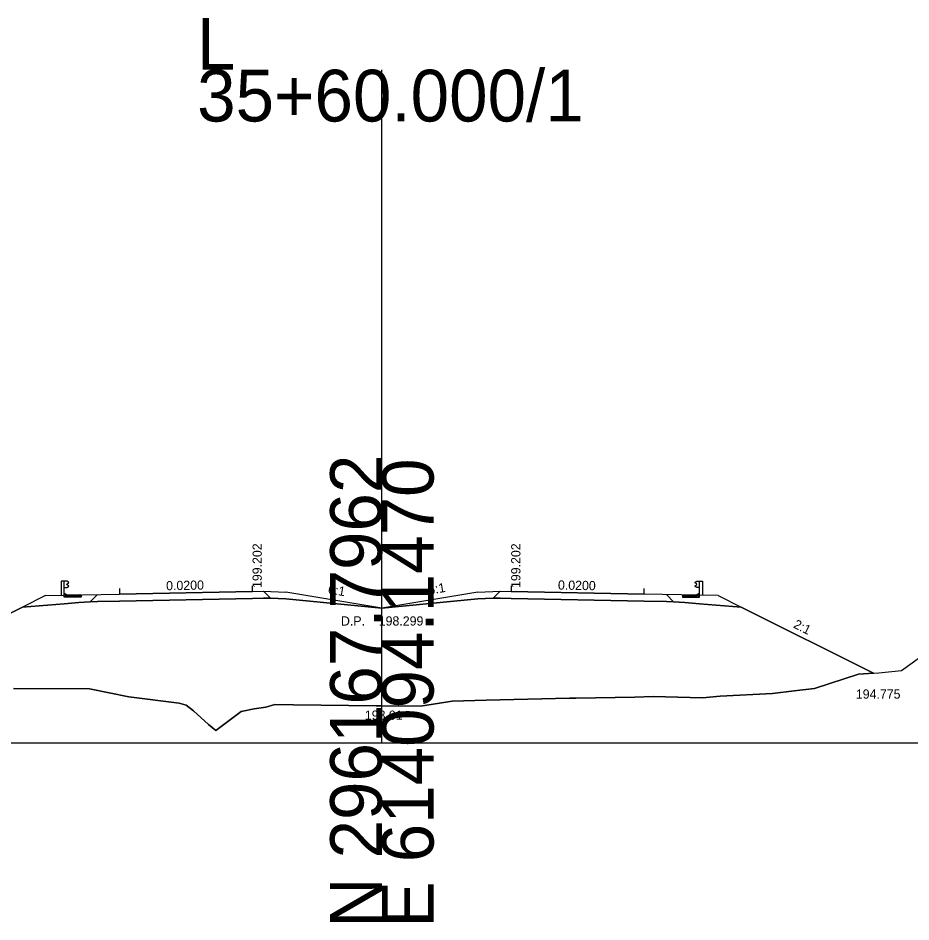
# Model space of a CAD drawing. Extents: x -81 to 616364, y 450 to 299952.
# Drawn here: x 541507.67 to 541556, y 118838.67 to 118887.61 of the extents above; entities that cross this region are included whole.
import ezdxf

# ---------------------------------------------------------------- set-up
doc = ezdxf.new("R2010")
doc.units = 0
for name, color, linetype in [('Exist XS Ground Line', 7, 'Continuous'), ('Old_Level_2', 7, 'Continuous'), ('Old_Level_3', 7, 'Continuous'), ('Old_Level_6', 7, 'Continuous'), ('Old_Level_63', 7, 'Continuous'), ('Prop XS Dump Level', 7, 'Continuous'), ('Prop XS Earthwork Shape', 7, 'Continuous'), ('Prop XS EOT Tick Mark', 7, 'Continuous'), ('Prop XS Finish Grade', 7, 'Continuous'), ('Prop XS Finish Grade Earthwork', 7, 'Continuous'), ('Prop XS Finish Grade Pavement', 7, 'Continuous'), ('Prop XS Label Text', 7, 'Continuous'), ('Prop XS Pvmt Edge Slope', 7, 'Continuous'), ('Prop XS Side Slope Text', 7, 'Continuous'), ('Prop XS Subgrade Earthwork', 7, 'Continuous')]:
    doc.layers.add(name, color=color, linetype=linetype)

msp = doc.modelspace()

# ---------------------------------------------------------------- linework, layer by layer
at = {"layer": 'Exist XS Ground Line'}
for p, q in [((541555.484, 118852.277), (541556.52, 118853.02)), ((541550.777, 118851.318), (541553.156, 118852.079)), ((541553.156, 118852.079), (541554.273, 118852.162)), ((541554.273, 118852.162), (541555.484, 118852.277)), ((541507.431, 118851.309), (541511.535, 118851.293)), ((541511.535, 118851.293), (541513.67, 118850.865)), ((541545.68, 118850.894), (541548.515, 118851.032)), ((541548.515, 118851.032), (541549.676, 118851.185)), ((541549.676, 118851.185), (541550.777, 118851.318)), ((541513.67, 118850.865), (541516.385, 118850.51)), ((541516.385, 118850.51), (541516.774, 118850.415)), ((541529.462, 118850.355), (541531.169, 118850.632)), ((541531.169, 118850.632), (541533.005, 118850.687)), ((541533.005, 118850.687), (541537.522, 118850.789)), ((541537.522, 118850.789), (541537.856, 118850.787)), ((541537.856, 118850.787), (541541.056, 118850.843)), ((541541.056, 118850.843), (541542.048, 118850.873)), ((541542.048, 118850.873), (541544.724, 118850.801)), ((541544.724, 118850.801), (541545.68, 118850.894)), ((541516.774, 118850.415), (541517.174, 118850.099)), ((541517.174, 118850.099), (541517.989, 118849.354)), ((541518.375, 118849.042), (541519.743, 118850.062)), ((541519.743, 118850.062), (541520.457, 118850.213)), ((541520.457, 118850.213), (541521.086, 118850.308)), ((541521.086, 118850.308), (541521.562, 118850.441)), ((541521.562, 118850.441), (541522.586, 118850.431)), ((541522.586, 118850.431), (541527.062, 118850.381)), ((541527.062, 118850.381), (541527.365, 118850.378)), ((541527.365, 118850.378), (541529.462, 118850.355)), ((541517.989, 118849.354), (541518.375, 118849.042))]:
    msp.add_line(p, q, dxfattribs=at)
at = {"layer": 'Old_Level_2'}
for p, q in [((541543.645, 118856.385), (541543.645, 118856.26)), ((541543.645, 118856.385), (541544.355, 118856.36)), ((541543.692, 118856.363), (541543.667, 118856.345)), ((541543.667, 118856.345), (541543.707, 118856.335)), ((541543.707, 118856.335), (541543.692, 118856.363)), ((541543.882, 118856.326), (541543.873, 118856.298)), ((541543.903, 118856.296), (541543.882, 118856.326)), ((541544.01, 118856.344), (541543.985, 118856.326)), ((541543.985, 118856.326), (541544.025, 118856.316)), ((541544.025, 118856.316), (541544.01, 118856.344)), ((541544.186, 118856.326), (541544.178, 118856.298)), ((541544.207, 118856.296), (541544.186, 118856.326)), ((541544.565, 118856.465), (541544.355, 118856.36)), ((541544.468, 118856.35), (541544.506, 118856.361)), ((541544.502, 118856.338), (541544.468, 118856.35)), ((541544.506, 118856.361), (541544.502, 118856.338)), ((541544.565, 118856.26), (541544.565, 118856.465)), ((541543.645, 118856.26), (541544.565, 118856.26)), ((541543.8, 118856.312), (541543.775, 118856.294)), ((541543.775, 118856.294), (541543.816, 118856.285)), ((541543.816, 118856.285), (541543.8, 118856.312)), ((541543.873, 118856.298), (541543.903, 118856.296)), ((541544.105, 118856.312), (541544.08, 118856.294)), ((541544.08, 118856.294), (541544.12, 118856.285)), ((541544.12, 118856.285), (541544.105, 118856.312)), ((541544.178, 118856.298), (541544.207, 118856.296)), ((541544.31, 118856.312), (541544.285, 118856.294)), ((541544.285, 118856.294), (541544.325, 118856.284)), ((541544.325, 118856.284), (541544.31, 118856.312)), ((541544.409, 118856.312), (541544.384, 118856.294)), ((541544.384, 118856.294), (541544.425, 118856.285)), ((541544.425, 118856.285), (541544.409, 118856.312))]:
    msp.add_line(p, q, dxfattribs=at)
for centre in [(541543.653, 118856.344), (541543.658, 118856.32), (541543.661, 118856.375), (541543.706, 118856.376), (541543.708, 118856.32), (541543.73, 118856.356), (541543.74, 118856.336), (541543.749, 118856.373), (541543.753, 118856.344), (541543.757, 118856.321), (541543.773, 118856.316), (541543.779, 118856.371), (541543.797, 118856.351), (541543.8, 118856.344), (541543.822, 118856.315), (541543.84, 118856.33), (541543.847, 118856.355), (541543.871, 118856.367), (541543.873, 118856.317), (541543.894, 118856.345), (541543.896, 118856.351), (541543.928, 118856.366), (541543.94, 118856.331), (541543.944, 118856.335), (541543.958, 118856.344), (541543.962, 118856.32), (541543.989, 118856.366), (541544.029, 118856.354), (541544.044, 118856.336), (541544.058, 118856.344), (541544.062, 118856.321), (541544.063, 118856.362), (541544.078, 118856.316), (541544.105, 118856.344), (541544.138, 118856.351), (541544.144, 118856.33), (541544.177, 118856.317), (541544.178, 118856.354), (541544.199, 118856.345), (541544.226, 118856.327), (541544.244, 118856.331), (541544.249, 118856.335), (541544.262, 118856.344), (541544.267, 118856.32), (541544.295, 118856.324), (541544.298, 118856.346), (541544.31, 118856.344), (541544.339, 118856.356), (541544.349, 118856.336), (541544.362, 118856.344), (541544.366, 118856.321), (541544.382, 118856.316), (541544.397, 118856.365), (541544.404, 118856.335), (541544.429, 118856.34), (541544.435, 118856.373), (541544.454, 118856.337), (541544.464, 118856.395), (541544.475, 118856.371), (541544.486, 118856.383), (541544.49, 118856.359), (541544.491, 118856.322), (541544.496, 118856.411), (541544.523, 118856.356), (541544.525, 118856.382), (541544.528, 118856.316), (541544.546, 118856.392), (541544.548, 118856.44), (541544.55, 118856.344), (541543.661, 118856.274), (541543.68, 118856.306), (541543.702, 118856.279), (541543.72, 118856.297), (541543.743, 118856.286), (541543.77, 118856.274), (541543.795, 118856.271), (541543.823, 118856.276), (541543.846, 118856.3), (541543.867, 118856.271), (541543.895, 118856.272), (541543.903, 118856.31), (541543.925, 118856.296), (541543.942, 118856.271), (541543.948, 118856.285), (541543.973, 118856.295), (541543.984, 118856.272), (541543.998, 118856.306), (541544.019, 118856.27), (541544.024, 118856.297), (541544.048, 118856.286), (541544.1, 118856.271), (541544.136, 118856.301), (541544.156, 118856.279), (541544.2, 118856.272), (541544.208, 118856.31), (541544.229, 118856.296), (541544.231, 118856.272), (541544.253, 118856.285), (541544.287, 118856.272), (541544.329, 118856.297), (541544.352, 118856.286), (541544.404, 118856.271), (541544.444, 118856.304), (541544.445, 118856.269), (541544.47, 118856.278), (541544.495, 118856.31), (541544.499, 118856.304), (541544.512, 118856.275), (541544.548, 118856.279)]:
    msp.add_circle(centre, 0.00196, dxfattribs=at)
for centre, start, end in [((541543.83, 118856.357), 170.2002, 7.8003), ((541543.947, 118856.355), 188.5188, 349.4817), ((541544.101, 118856.351), 124.5837, 53.4168), ((541544.201, 118856.351), 206.3348, 331.6657), ((541544.251, 118856.355), 269.9741, 330.0388), ((541544.536, 118856.406), 131.0057, 228.9943), ((541543.644, 118856.285), 307.9938, 52.0062), ((541543.738, 118856.259), 49.2889, 130.7111), ((541543.838, 118856.26), 21.9976, 158.0024), ((541544.043, 118856.259), 49.2889, 130.7111), ((541544.142, 118856.26), 21.9976, 158.0024), ((541544.347, 118856.259), 49.2889, 130.7111)]:
    msp.add_arc(centre, 0.00196, start, end, dxfattribs=at)
at = {"layer": 'Old_Level_3'}
for p, q in [((541510.165, 118856.465), (541510.375, 118856.36)), ((541510.165, 118856.26), (541510.165, 118856.465)), ((541510.224, 118856.361), (541510.228, 118856.338)), ((541510.261, 118856.35), (541510.224, 118856.361)), ((541510.228, 118856.338), (541510.261, 118856.35)), ((541511.085, 118856.385), (541510.375, 118856.36)), ((541510.523, 118856.296), (541510.544, 118856.326)), ((541510.544, 118856.326), (541510.552, 118856.298)), ((541510.705, 118856.316), (541510.72, 118856.344)), ((541510.745, 118856.326), (541510.705, 118856.316)), ((541510.72, 118856.344), (541510.745, 118856.326)), ((541510.827, 118856.296), (541510.848, 118856.326)), ((541510.848, 118856.326), (541510.856, 118856.298)), ((541511.022, 118856.335), (541511.038, 118856.363)), ((541511.063, 118856.345), (541511.022, 118856.335)), ((541511.038, 118856.363), (541511.063, 118856.345)), ((541511.085, 118856.385), (541511.085, 118856.26)), ((541511.085, 118856.26), (541510.165, 118856.26)), ((541510.305, 118856.285), (541510.32, 118856.312)), ((541510.345, 118856.294), (541510.305, 118856.285)), ((541510.32, 118856.312), (541510.345, 118856.294)), ((541510.405, 118856.284), (541510.42, 118856.312)), ((541510.445, 118856.294), (541510.405, 118856.284)), ((541510.42, 118856.312), (541510.445, 118856.294)), ((541510.552, 118856.298), (541510.523, 118856.296)), ((541510.609, 118856.285), (541510.625, 118856.312)), ((541510.65, 118856.294), (541510.609, 118856.285)), ((541510.625, 118856.312), (541510.65, 118856.294)), ((541510.856, 118856.298), (541510.827, 118856.296)), ((541510.914, 118856.285), (541510.929, 118856.312)), ((541510.954, 118856.294), (541510.914, 118856.285)), ((541510.929, 118856.312), (541510.954, 118856.294))]:
    msp.add_line(p, q, dxfattribs=at)
for centre in [(541510.179, 118856.344), (541510.182, 118856.44), (541510.184, 118856.392), (541510.201, 118856.316), (541510.205, 118856.382), (541510.206, 118856.356), (541510.234, 118856.411), (541510.238, 118856.322), (541510.24, 118856.359), (541510.244, 118856.383), (541510.254, 118856.371), (541510.266, 118856.395), (541510.276, 118856.337), (541510.294, 118856.373), (541510.301, 118856.34), (541510.326, 118856.335), (541510.333, 118856.365), (541510.348, 118856.316), (541510.363, 118856.321), (541510.368, 118856.344), (541510.381, 118856.336), (541510.391, 118856.356), (541510.42, 118856.344), (541510.431, 118856.346), (541510.434, 118856.324), (541510.463, 118856.32), (541510.467, 118856.344), (541510.481, 118856.335), (541510.486, 118856.331), (541510.503, 118856.327), (541510.531, 118856.345), (541510.551, 118856.354), (541510.552, 118856.317), (541510.585, 118856.33), (541510.592, 118856.351), (541510.625, 118856.344), (541510.652, 118856.316), (541510.666, 118856.362), (541510.668, 118856.321), (541510.672, 118856.344), (541510.686, 118856.336), (541510.7, 118856.354), (541510.741, 118856.366), (541510.768, 118856.32), (541510.772, 118856.344), (541510.785, 118856.335), (541510.79, 118856.331), (541510.802, 118856.366), (541510.833, 118856.351), (541510.835, 118856.345), (541510.857, 118856.317), (541510.859, 118856.367), (541510.883, 118856.355), (541510.89, 118856.33), (541510.908, 118856.315), (541510.929, 118856.344), (541510.933, 118856.351), (541510.951, 118856.371), (541510.957, 118856.316), (541510.972, 118856.321), (541510.977, 118856.344), (541510.98, 118856.373), (541510.99, 118856.336), (541511, 118856.356), (541511.022, 118856.32), (541511.024, 118856.376), (541511.069, 118856.375), (541511.072, 118856.32), (541511.076, 118856.344), (541510.182, 118856.279), (541510.218, 118856.275), (541510.231, 118856.304), (541510.234, 118856.31), (541510.259, 118856.278), (541510.284, 118856.269), (541510.285, 118856.304), (541510.325, 118856.271), (541510.377, 118856.286), (541510.401, 118856.297), (541510.443, 118856.272), (541510.477, 118856.285), (541510.499, 118856.272), (541510.5, 118856.296), (541510.522, 118856.31), (541510.53, 118856.272), (541510.573, 118856.279), (541510.594, 118856.301), (541510.63, 118856.271), (541510.682, 118856.286), (541510.705, 118856.297), (541510.711, 118856.27), (541510.732, 118856.306), (541510.746, 118856.272), (541510.757, 118856.295), (541510.781, 118856.285), (541510.788, 118856.271), (541510.805, 118856.296), (541510.826, 118856.31), (541510.835, 118856.272), (541510.863, 118856.271), (541510.884, 118856.3), (541510.907, 118856.276), (541510.934, 118856.271), (541510.959, 118856.274), (541510.986, 118856.286), (541511.01, 118856.297), (541511.028, 118856.279), (541511.05, 118856.306), (541511.069, 118856.274)]:
    msp.add_circle(centre, 0.00196, dxfattribs=at)
for centre, start, end in [((541510.194, 118856.406), 311.0057, 48.9943), ((541510.479, 118856.355), 209.9612, 270.0259), ((541510.529, 118856.351), 208.3343, 333.6652), ((541510.628, 118856.351), 126.5832, 55.4163), ((541510.783, 118856.355), 190.5183, 351.4812), ((541510.9, 118856.357), 172.1997, 9.7998), ((541510.382, 118856.259), 49.2889, 130.7111), ((541510.587, 118856.26), 21.9976, 158.0024), ((541510.687, 118856.259), 49.2889, 130.7111), ((541510.892, 118856.26), 21.9976, 158.0024), ((541510.991, 118856.259), 49.2889, 130.7111), ((541511.086, 118856.285), 127.9938, 232.0062)]:
    msp.add_arc(centre, 0.00196, start, end, dxfattribs=at)
at = {"layer": 'Old_Level_6'}
for p, q in [((541513.165, 118856.423), (541520.365, 118856.567)), ((541534.365, 118856.567), (541541.565, 118856.423))]:
    msp.add_line(p, q, dxfattribs=at)
at = {"layer": 'Old_Level_63'}
for p, q in [((541527.365, 118848.365), (541527.365, 118884.812)), ((541452.365, 118848.365), (541527.365, 118848.365)), ((541527.365, 118848.365), (541602.365, 118848.365))]:
    msp.add_line(p, q, dxfattribs=at)
at = {"layer": 'Prop XS Dump Level'}
for p, q in [((541513.165, 118856.423), (541520.365, 118856.567)), ((541534.365, 118856.567), (541541.565, 118856.423))]:
    msp.add_line(p, q, dxfattribs=at)
at = {"layer": 'Prop XS Earthwork Shape'}
for points in [[(541507.431, 118851.309), (541511.535, 118851.293), (541513.67, 118850.865), (541516.385, 118850.51), (541516.774, 118850.415), (541517.174, 118850.099), (541517.989, 118849.354), (541518.375, 118849.042), (541519.743, 118850.062), (541520.457, 118850.213), (541521.086, 118850.308), (541521.562, 118850.441), (541522.586, 118850.431), (541527.062, 118850.381), (541527.365, 118850.378), (541529.462, 118850.355), (541531.169, 118850.632), (541533.005, 118850.687), (541537.522, 118850.789), (541537.856, 118850.787), (541541.056, 118850.843), (541542.048, 118850.873), (541544.724, 118850.801), (541545.68, 118850.894), (541548.515, 118851.032), (541549.676, 118851.185), (541550.777, 118851.318), (541553.156, 118852.079), (541553.971, 118852.14), (541546.814, 118855.718), (541544.565, 118855.898), (541543.765, 118855.962), (541543.153, 118856.011), (541542.765, 118856.019), (541541.565, 118856.043), (541534.365, 118856.187), (541533.765, 118856.199), (541533.392, 118856.206), (541532.565, 118856.173), (541527.365, 118855.664), (541522.165, 118856.173), (541521.337, 118856.206), (541520.965, 118856.199), (541520.365, 118856.187), (541513.165, 118856.043), (541511.965, 118856.019), (541511.577, 118856.011), (541510.965, 118855.962), (541510.165, 118855.898), (541507.915, 118855.718), (541500.505, 118852.013)], [(541507.431, 118851.309), (541511.535, 118851.293), (541513.67, 118850.865), (541516.385, 118850.51), (541516.774, 118850.415), (541517.174, 118850.099), (541517.989, 118849.354), (541518.375, 118849.042), (541519.743, 118850.062), (541520.457, 118850.213), (541521.086, 118850.308), (541521.562, 118850.441), (541522.586, 118850.431), (541527.062, 118850.381), (541527.365, 118850.378), (541529.462, 118850.355), (541531.169, 118850.632), (541533.005, 118850.687), (541537.522, 118850.789), (541537.856, 118850.787), (541541.056, 118850.843), (541542.048, 118850.873), (541544.724, 118850.801), (541545.68, 118850.894), (541548.515, 118851.032), (541549.676, 118851.185), (541550.777, 118851.318), (541553.156, 118852.079), (541553.971, 118852.14), (541546.814, 118855.718), (541544.565, 118855.898), (541543.765, 118855.962), (541543.153, 118856.011), (541542.765, 118856.019), (541541.565, 118856.043), (541534.365, 118856.187), (541533.765, 118856.199), (541533.392, 118856.206), (541532.565, 118856.173), (541527.365, 118855.664), (541522.165, 118856.173), (541521.337, 118856.206), (541520.965, 118856.199), (541520.365, 118856.187), (541513.165, 118856.043), (541511.965, 118856.019), (541511.577, 118856.011), (541510.965, 118855.962), (541510.165, 118855.898), (541507.915, 118855.718), (541500.505, 118852.013)], [(541500.505, 118852.013), (541507.915, 118855.718), (541510.165, 118855.898), (541510.965, 118855.962), (541511.577, 118856.011), (541511.965, 118856.019), (541513.165, 118856.043), (541520.365, 118856.187), (541520.965, 118856.199), (541521.337, 118856.206), (541522.165, 118856.173), (541527.365, 118855.664), (541532.565, 118856.173), (541533.392, 118856.206), (541533.765, 118856.199), (541534.365, 118856.187), (541541.565, 118856.043), (541542.765, 118856.019), (541543.153, 118856.011), (541543.765, 118855.962), (541544.565, 118855.898), (541546.814, 118855.718), (541553.971, 118852.14), (541553.156, 118852.079), (541550.777, 118851.318), (541549.676, 118851.185), (541548.515, 118851.032), (541545.68, 118850.894), (541544.724, 118850.801), (541542.048, 118850.873), (541541.056, 118850.843), (541537.856, 118850.787), (541537.522, 118850.789), (541533.005, 118850.687), (541531.169, 118850.632), (541529.462, 118850.355), (541527.365, 118850.378), (541527.062, 118850.381), (541522.586, 118850.431), (541521.562, 118850.441), (541521.086, 118850.308), (541520.457, 118850.213), (541519.743, 118850.062), (541518.375, 118849.042), (541517.989, 118849.354), (541517.174, 118850.099), (541516.774, 118850.415), (541516.385, 118850.51), (541513.67, 118850.865), (541511.535, 118851.293), (541507.431, 118851.309)], [(541500.505, 118852.013), (541507.915, 118855.718), (541510.165, 118855.898), (541510.965, 118855.962), (541511.577, 118856.011), (541511.965, 118856.019), (541513.165, 118856.043), (541520.365, 118856.187), (541520.965, 118856.199), (541521.337, 118856.206), (541522.165, 118856.173), (541527.365, 118855.664), (541532.565, 118856.173), (541533.392, 118856.206), (541533.765, 118856.199), (541534.365, 118856.187), (541541.565, 118856.043), (541542.765, 118856.019), (541543.153, 118856.011), (541543.765, 118855.962), (541544.565, 118855.898), (541546.814, 118855.718), (541553.971, 118852.14), (541553.156, 118852.079), (541550.777, 118851.318), (541549.676, 118851.185), (541548.515, 118851.032), (541545.68, 118850.894), (541544.724, 118850.801), (541542.048, 118850.873), (541541.056, 118850.843), (541537.856, 118850.787), (541537.522, 118850.789), (541533.005, 118850.687), (541531.169, 118850.632), (541529.462, 118850.355), (541527.365, 118850.378), (541527.062, 118850.381), (541522.586, 118850.431), (541521.562, 118850.441), (541521.086, 118850.308), (541520.457, 118850.213), (541519.743, 118850.062), (541518.375, 118849.042), (541517.989, 118849.354), (541517.174, 118850.099), (541516.774, 118850.415), (541516.385, 118850.51), (541513.67, 118850.865), (541511.535, 118851.293), (541507.431, 118851.309)]]:
    msp.add_lwpolyline(points, dxfattribs=at)
at = {"layer": 'Prop XS EOT Tick Mark'}
for p, q in [((541520.365, 118856.567), (541520.365, 118856.872)), ((541534.365, 118856.872), (541534.365, 118856.567)), ((541513.165, 118856.728), (541513.165, 118856.423)), ((541541.565, 118856.423), (541541.565, 118856.728))]:
    msp.add_line(p, q, dxfattribs=at)
at = {"layer": 'Prop XS Finish Grade'}
for p, q in [((541509.165, 118856.343), (541507.916, 118855.718)), ((541509.165, 118856.343), (541510.165, 118856.363)), ((541520.965, 118856.579), (541522.165, 118856.531)), ((541527.365, 118855.664), (541522.165, 118856.531)), ((541532.565, 118856.531), (541527.365, 118855.664)), ((541532.565, 118856.531), (541533.765, 118856.579)), ((541545.565, 118856.343), (541544.565, 118856.363)), ((541545.565, 118856.343), (541546.814, 118855.718))]:
    msp.add_line(p, q, dxfattribs=at)
at = {"layer": 'Prop XS Finish Grade Earthwork'}
for p, q in [((541507.916, 118855.718), (541500.505, 118852.013)), ((541546.814, 118855.718), (541553.971, 118852.14))]:
    msp.add_line(p, q, dxfattribs=at)
at = {"layer": 'Prop XS Finish Grade Pavement'}
for p, q in [((541510.165, 118856.363), (541513.165, 118856.423)), ((541520.365, 118856.567), (541513.165, 118856.423)), ((541520.365, 118856.567), (541520.965, 118856.579)), ((541533.765, 118856.579), (541534.365, 118856.567)), ((541541.565, 118856.423), (541534.365, 118856.567)), ((541544.565, 118856.363), (541541.565, 118856.423))]:
    msp.add_line(p, q, dxfattribs=at)
at = {"layer": 'Prop XS Label Text'}
for p, q in [((541510.165, 118857.125), (541510.012, 118857.125)), ((541510.012, 118857.125), (541510.012, 118856.363)), ((541510.317, 118857.125), (541510.165, 118857.125)), ((541510.165, 118856.363), (541510.165, 118857.125)), ((541510.406, 118857.064), (541510.317, 118857.125)), ((541510.317, 118856.966), (541510.406, 118857.027)), ((541510.317, 118856.938), (541510.317, 118856.966)), ((541510.406, 118856.877), (541510.317, 118856.938)), ((541510.317, 118856.779), (541510.406, 118856.84)), ((541510.415, 118857.046), (541510.406, 118857.064)), ((541510.406, 118857.027), (541510.415, 118857.046)), ((541510.415, 118856.858), (541510.406, 118856.877)), ((541510.406, 118856.84), (541510.415, 118856.858)), ((541544.315, 118857.046), (541544.324, 118857.064)), ((541544.324, 118857.027), (541544.315, 118857.046)), ((541544.315, 118856.858), (541544.324, 118856.877)), ((541544.324, 118856.84), (541544.315, 118856.858)), ((541544.324, 118857.064), (541544.412, 118857.125)), ((541544.412, 118856.966), (541544.324, 118857.027)), ((541544.324, 118856.877), (541544.412, 118856.938)), ((541544.412, 118856.779), (541544.324, 118856.84)), ((541544.412, 118857.125), (541544.565, 118857.125)), ((541544.412, 118856.938), (541544.412, 118856.966)), ((541544.565, 118856.363), (541544.565, 118857.125)), ((541544.565, 118857.125), (541544.717, 118857.125)), ((541544.717, 118857.125), (541544.717, 118856.363)), ((541510.165, 118856.779), (541510.317, 118856.779)), ((541544.565, 118856.779), (541544.412, 118856.779))]:
    msp.add_line(p, q, dxfattribs=at)
at = {"layer": 'Prop XS Pvmt Edge Slope'}
for p, q in [((541511.577, 118856.011), (541511.965, 118856.399)), ((541520.965, 118856.579), (541521.337, 118856.206)), ((541533.392, 118856.206), (541533.765, 118856.579)), ((541542.765, 118856.399), (541543.153, 118856.011))]:
    msp.add_line(p, q, dxfattribs=at)
at = {"layer": 'Prop XS Subgrade Earthwork'}
for p, q in [((541507.915, 118855.718), (541510.165, 118855.898)), ((541510.165, 118855.898), (541510.965, 118855.962)), ((541510.965, 118855.962), (541511.577, 118856.011)), ((541511.577, 118856.011), (541511.965, 118856.019)), ((541511.965, 118856.019), (541513.165, 118856.043)), ((541520.365, 118856.187), (541513.165, 118856.043)), ((541520.365, 118856.187), (541520.965, 118856.199)), ((541520.965, 118856.199), (541521.337, 118856.206)), ((541521.337, 118856.206), (541522.165, 118856.173)), ((541527.365, 118855.664), (541522.165, 118856.173)), ((541527.365, 118855.664), (541532.565, 118856.173)), ((541532.565, 118856.173), (541533.392, 118856.206)), ((541533.392, 118856.206), (541533.765, 118856.199)), ((541533.765, 118856.199), (541534.365, 118856.187)), ((541541.565, 118856.043), (541534.365, 118856.187)), ((541541.565, 118856.043), (541542.765, 118856.019)), ((541542.765, 118856.019), (541543.153, 118856.011)), ((541543.153, 118856.011), (541543.765, 118855.962)), ((541543.765, 118855.962), (541544.565, 118855.898)), ((541544.565, 118855.898), (541546.814, 118855.718))]:
    msp.add_line(p, q, dxfattribs=at)

# ---------------------------------------------------------------- texts
at = {"layer": 'Old_Level_63'}
for s, p in [('L', (541517.356, 118884.812)), ('35+60.000/1', (541517.365, 118882.012))]:
    msp.add_text(s, height=2.8, dxfattribs=at).set_placement(p)
for s, p in [('N 296167.7962', (541527.365, 118838.365)), ('E 614094.1470', (541530.165, 118838.365))]:
    msp.add_text(s, height=2.8, rotation=90, dxfattribs=at).set_placement(p)
at = {"layer": 'Prop XS Dump Level'}
for s, p in [('Case4', (541510.165, 118856.363)), ('Case1', (541522.165, 118856.519)), ('MGSP-L', (541522.165, 118856.519)), ('Case1', (541532.565, 118856.519)), ('MGSP-R', (541532.565, 118856.519)), ('Case4', (541544.521, 118856.363)), ('MGDP', (541527.365, 118855.652))]:
    msp.add_text(s, height=0.0122, dxfattribs=at).set_placement(p)
at = {"layer": 'Prop XS Side Slope Text'}
for s, rotation, p in [(' 199.202', 90, (541520.865, 118856.567)), (' 199.20', 90, (541520.865, 118856.567)), (' 199.202', 90, (541534.865, 118856.567)), (' 199.20', 90, (541534.865, 118856.567)), ('0.0200', 1.1458, (541515.692, 118856.626)), ('6:1', 350.5377, (541524.423, 118856.458)), ('6:1', 9.4623, (541529.916, 118856.393)), ('0.0200', 358.8542, (541536.892, 118856.669)), ('2:1', 333.435, (541549.6, 118854.626))]:
    msp.add_text(s, height=0.5, rotation=rotation, dxfattribs=at).set_placement(p)
for s, p in [('D.P.    198.299', (541525.151, 118854.718)), ('194.775', (541553.021, 118850.76)), ('193.01', (541526.444, 118849.618))]:
    msp.add_text(s, height=0.5, dxfattribs=at).set_placement(p)

doc.saveas('drawing.dxf')
